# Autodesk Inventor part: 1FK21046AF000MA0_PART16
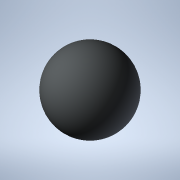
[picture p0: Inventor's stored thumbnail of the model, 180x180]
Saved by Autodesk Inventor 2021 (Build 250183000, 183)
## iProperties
Created: 2025-04
Part Number: 1FK21046AF000MA0_PART16
Material: Generic
Catalog Web Link: www.3dfindit.com
Description: -Servo synchronous motor
Document SubType Name: Modeling
Designer: psAdmin
Mass: 0.137258 g
Surface Area: 1.2868 cm^2
Volume: 0.137258 cm^3
Density: 1 g/cm^3
Appearance: PSOLRGB-212-217-219
Category: PARTsolutions
Title: 1FK21046AF000MA0_PART16
Author: Cadenas PARTsolutions
Comments: Servo synchronous motor
Sending System: PARTsolutions
Preprocessor: ST-DEVELOPER v19.3
PSOL_IDENT_0: {$CADENAS_DATA/23d-libs/siemens_ag/_cat_/1c/1f/1fk21046af000ma0.prj},216 {VTYP=3D},{NB=1FK21046AF000
PSOL_IDENT_1: MA0_PART16},{LINA=1FK21046AF000MA0_PART16},{NN=1FK21046AF000MA0_PART16},{NOPRJ=TRUE},{DATE=19.08.202
PSOL_IDENT_2: 5 14:00:28},{GEOMDATE=30.07.2025 02:02:08},{VERSION=},{LINEID=10},{WBVAR=},{WBNUMERIC=}  {NB=1FK2104
PSOL_IDENT_3: 6AF000MA0_PART16},{LINA=1FK21046AF000MA0_PART16},{KT=DUMMY},{PREVIEW=../../../_pool_/cb/72/p_d211_xx
PSOL_IDENT_4: _00434j.png},{DESCSHORT=SIMOTICS S-1FK2 HD, SINAMICS S210 3AC 400V-480V, 3.2 Nm, 3000 rpm},{DESCLONG=
PSOL_IDENT_5: SIMOTICS S-1FK2 HD servo motor M0=3.2 Nm; PN = 1 kW at nN=3000 rpm (380-480 V); PN = 0.5 kW at nN=15
PSOL_IDENT_6: 00 rpm (200-240 V); degree of protection IP64; cylindrical shaft D19x40mm; absolute encoder 22-bit +
PSOL_IDENT_7: 12-bit multiturn (encoder AM22DQC); with OCC interface; plug size M17, rotatable; SIMOTICS S-1FK2 s
PSOL_IDENT_8: ervomotorfor a wide range of uses in industrial environments. SIMOTICS S‑1FK2 servomotors are compac
PSOL_IDENT_9: t synchronous motors with a high dynamic performance that set themselves apart as a result of their
PSOL_IDENT_10: high power density, degree of protection and overload capability. The motors are available in two va
PSOL_IDENT_11: riants: as High Dynamic variant (highest dynamic performance as a result of the low intrinsic moment
PSOL_IDENT_12: of inertia for applications demanding a high dynamic performance with low moved masses) - and as Co
PSOL_IDENT_13: mpact variant (precise and stable closed-loop control for medium up to large moved masses as a resul
PSOL_IDENT_14: t of a medium intrinsic moment of inertia). SIMOTICSS‑1FK2 servomotors fully exploit their strengths
PSOL_IDENT_15: in a system with the SINAMICSS210 frequency converter and simple connection using the one cable con
PSOL_IDENT_16: nection (OCC). Advantages include the short control and positioning times, fast and precise correcti
PSOL_IDENT_17: on of disturbing quantities as well as stable control with a high dynamic performance. The servo mot
PSOL_IDENT_18: ors can be configured to address a wide range of requirements. For example with and without holding
PSOL_IDENT_19: brake, IP64 or IP65 degree of protection, singleturn or multiturn absolute encoders - to name just a
PSOL_IDENT_20: few. Further, the servomotors are available in different shaft heights extending from 20 to 100. A
PSOL_IDENT_21: shaft sealing ring is available to achieve an IP65 degree of protection and for subsequent mounting
PSOL_IDENT_22: at the motor or as spare part. SIMOTICS - the optimum motor for each and every motion control applic
PSOL_IDENT_23: ation.},{INTNO=195125049666},{SUPPLIERALTNO=1FK2104-6AF00-0MA0},{MANUID=1FK21046AF000MA0},{MANUNAME=
PSOL_IDENT_24: Siemens},{MANUTYPEDESC=Synchronous motor 1FK2-HD 3.2 NM},{AAU732=SIMOTICS},{AAO057=S-1FK2},{AAU734=S
PSOL_IDENT_25: IMOTICS S-1FK2 HD servo motor M0=3.2 Nm; PN = 1 kW at nN=3000 rpm (380-480 V); PN = 0.5 kW at nN=150
PSOL_IDENT_26: 0 rpm (200-240 V); degree of protection IP64; cylindrical shaft D19x40mm; absolute encoder 22-bit +
PSOL_IDENT_27: 12-bit multiturn (encoder AM22DQC); with OCC interface; plug size M17, rotatable;},{AAW338=Synchrono
PSOL_IDENT_28: us motor 1FK2-HD 3.2 NM},{AAO742=SIMOTICS},{AAO663=4042948694374},{NOCUPEROU=1},{PRICEQUANTITY=1},{Q
PSOL_IDENT_29: UANTITYMIN=1},{QUANTITYINT=1},{CTN=85015220},{COO=DE},{AAO676=1FK2104-6AF00-0MA0},{AAO677=Siemens AG
PSOL_IDENT_30: },{ORDERUNIT=C62},{CONTENTUNIT=C62}
NB: 1FK21046AF000MA0_PART16
NT: Servo synchronous motor
NBSYN: $MANUID._PART16
LINA: 1FK21046AF000MA0_PART16
CATALOG: SIEMENS
PREVIEW: ../../../_pool_/cb/72/p_d211_xx_00434j.png
DESCSHORT: SIMOTICS S-1FK2 HD, SINAMICS S210 3AC 400V-480V, 3.2 Nm, 3000 rpm
DESCLONG: SIMOTICS S-1FK2 HD servo motor M0=3.2 Nm; PN = 1 kW at nN=3000 rpm (380-480 V); PN = 0.5 kW at nN=1500 rpm (200-240 V); degree of protection IP64; cylindrical s
INTNO: 195125049666
SUPPLIERALTNO: 1FK2104-6AF00-0MA0
MANUID: 1FK21046AF000MA0
MANUNAME: Siemens
MANUTYPEDESC: Synchronous motor 1FK2-HD 3.2 NM
AAU732: SIMOTICS
AAO057: S-1FK2
AAU734: SIMOTICS S-1FK2 HD servo motor M0=3.2 Nm; PN = 1 kW at nN=3000 rpm (380-480 V); PN = 0.5 kW at nN=1500 rpm (200-240 V); degree of protection IP64; cylindrical s
AAW338: Synchronous motor 1FK2-HD 3.2 NM
AAO742: SIMOTICS
AAO663: 4042948694374.0
NOCUPEROU: 1
PRICEQUANTITY: 1
QUANTITYMIN: 1
QUANTITYINT: 1
CTN: 85015220
COO: DE
ARTICLENO: 1FK21046AF000MA0_PART16
BOMINFO: 1FK21046AF000MA0_PART16
CREATOR: CADENAS GmbH
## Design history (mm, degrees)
feature "2025_04_17_15_39_11_0412"
body "Solid1"
